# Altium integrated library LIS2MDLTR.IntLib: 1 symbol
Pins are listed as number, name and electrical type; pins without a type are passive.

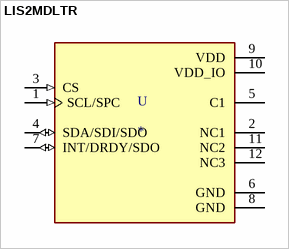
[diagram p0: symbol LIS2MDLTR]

## LIS2MDLTR
designator U
Magnetoresistive Sensor X, Y, Z Axis 12-LGA _2x2_; MP: LIS2MDLTR; MF: STMicroelectronics
footprint PQFN50P200X200X70-12N
pins: 1 SCL/SPC (in), 2 NC1, 3 CS (in), 4 SDA/SDI/SDO (io), 5 C1, 6 GND (power), 7 INT/DRDY/SDO (io), 8 GND (power), 9 VDD (power), 10 VDD_IO (power), 11 NC2, 12 NC3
